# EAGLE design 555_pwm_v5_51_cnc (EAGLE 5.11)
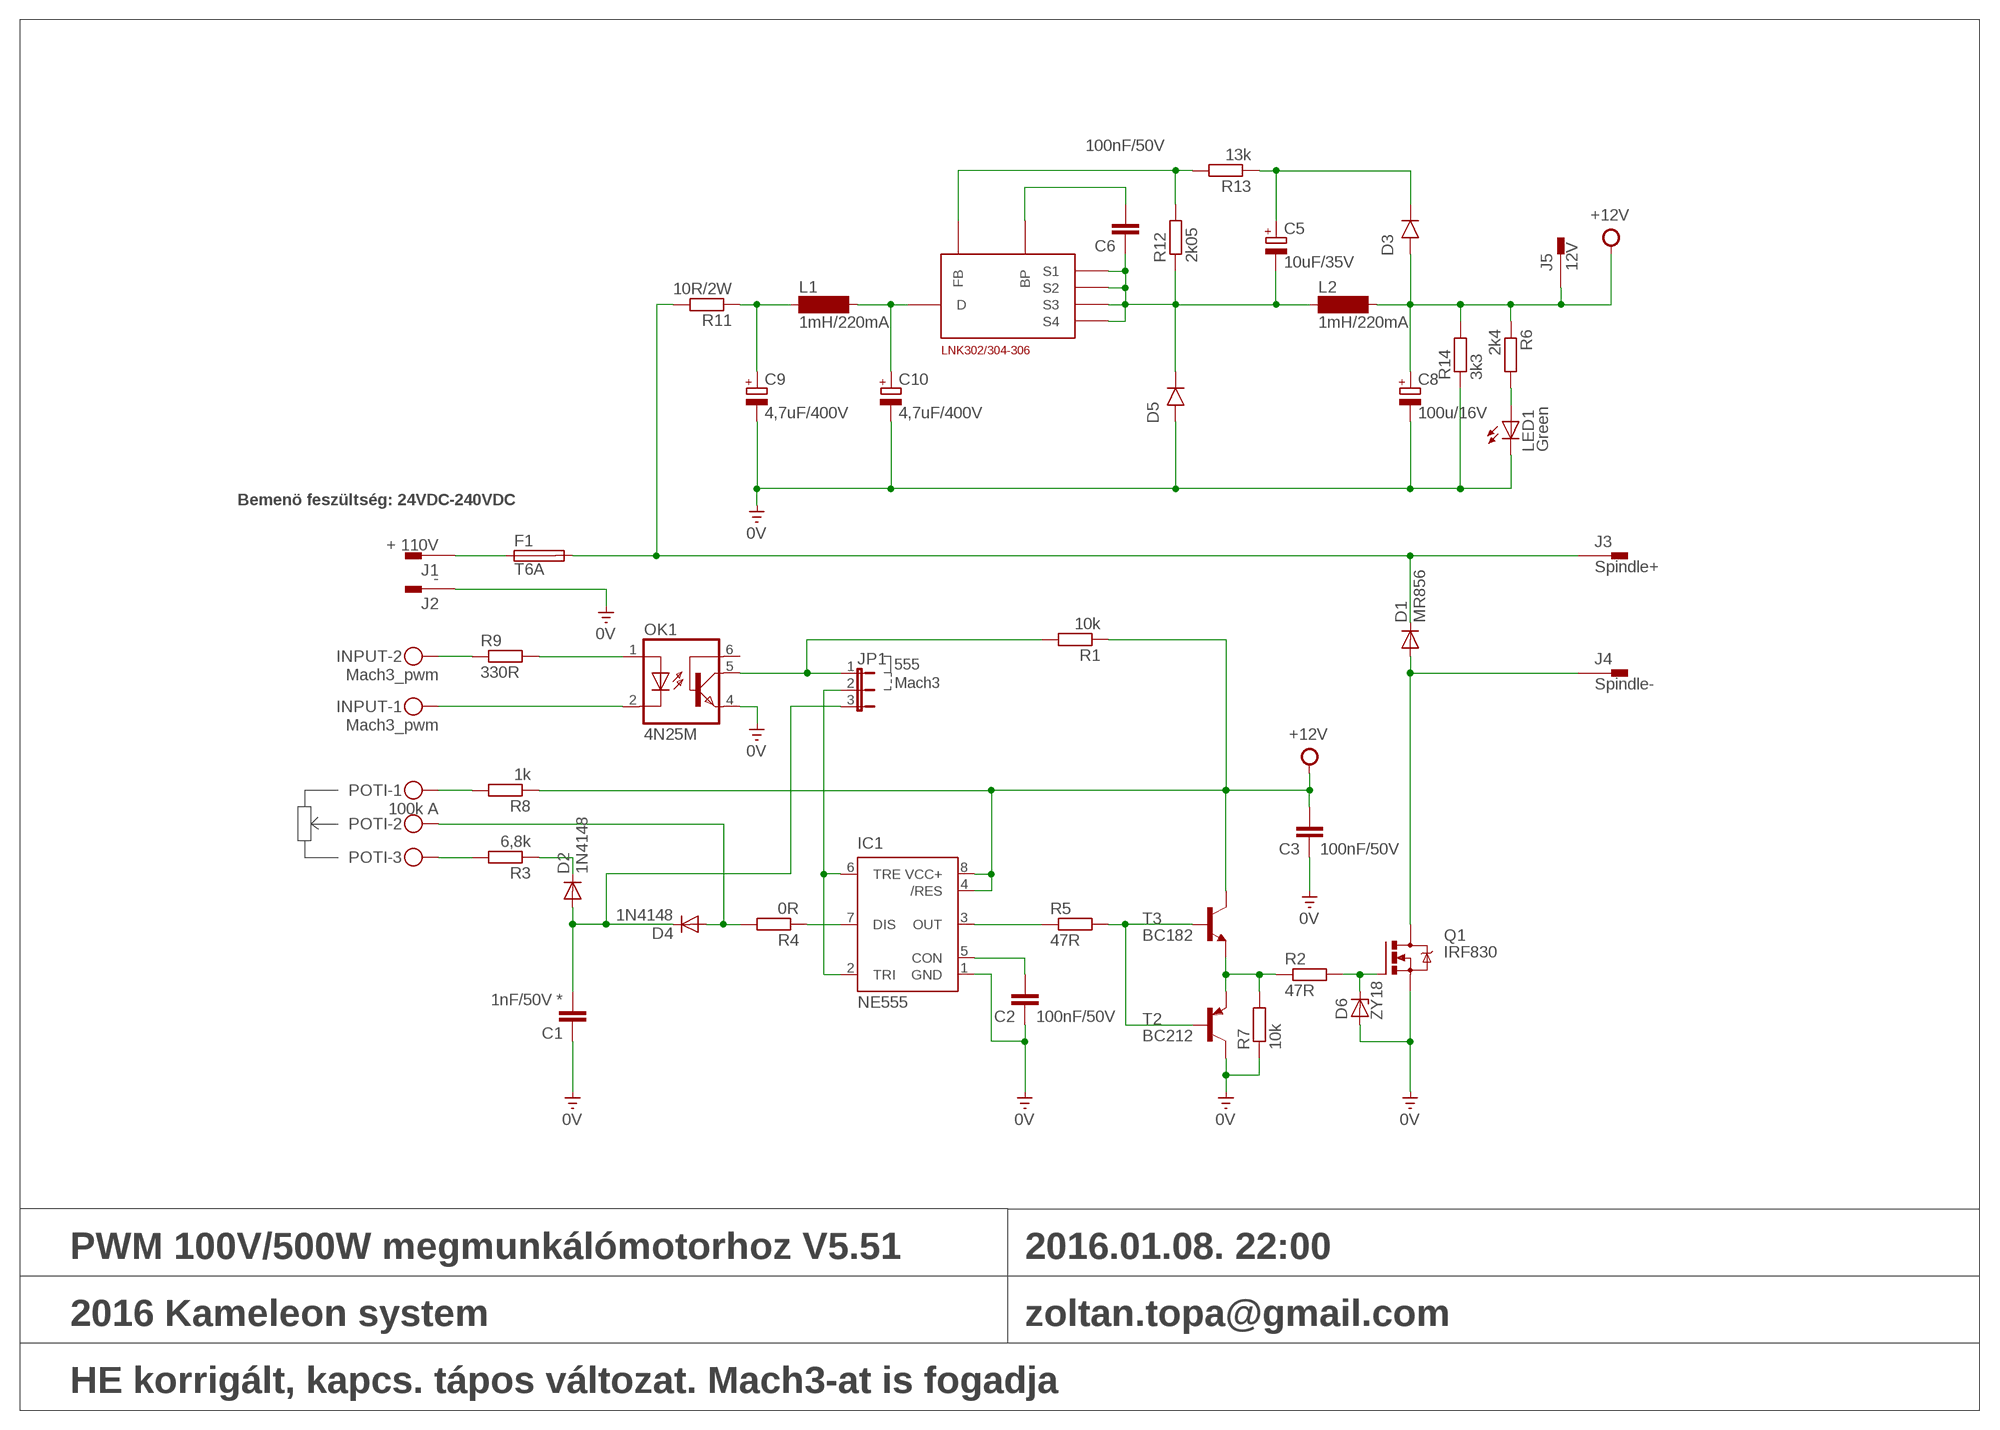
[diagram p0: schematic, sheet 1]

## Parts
C1  1nF/50V *  C-EU025_050-055X075  [C025_050-055X075]
C2  100nF/50V  C-EU025_050-055X075  [C025_050-055X075]
C3  100nF/50V  C-EU025_050-055X075  [C025_050-055X075]
C5  10uF/35V  CPOL-EUE2.5-5  [E2,5-5]
C6  100nF/50V  C-EU025_050-055X075  [C025_050-055X075]
C8  100u/16V  CPOL-EUE2.5-7  [E2,5-7]
C9  4,7uF/400V  CPOL-EUE2.5-7  [E2,5-7]
C10  4,7uF/400V  CPOL-EUE2.5-7  [E2,5-7]
D1  MR856  1N5400  [DO201-15]
D2  1N4148  1N4148DO35-10  [DO35-10]
D3  1N4007  1N4001  [DO41-10]
D4  1N4148  1N4148DO35-10  [DO35-10]
D5  1N4007  1N4001  [DO41-10]
D6  ZY18  ZENER-DIODEDO35Z10  [DO35Z10]
F1  T6A  SH22,5A  [SH22,5A]
IC1  NE555  [DIL-08]
INPUT  Mach3_pwm  MKDSN1,5/2-5,08  [MKDSN1,5/2-5,08]
J1  + 110V  PIN2F061.100  [F061.100]
J2  -  PIN2F061.100  [F061.100]
J3  Spindle+  PIN2F061.100  [F061.100]
J4  Spindle-  PIN2F061.100  [F061.100]
J5  12V  PIN2F061.100  [F061.100]
JP1  JP2E  [JP2]
L1  1mH/220mA  BS11  [BS11]
L2  1mH/220mA  BS11  [BS11]
LED1  Green  LED5MM  [LED5MM]
LNK304PN  LNK304PN  LNK302/304-306DIL_08  [DIL08_LNK]
OK1  4N25M  [DIL06]
POTI  100k A  MKDSN1,5/3-5,08  [MKDSN1,5/3-5,08]
Q1  IRF830  IRF540  [TO220BV]
R1  10k  R-EU_0309/10  [0309/10]
R2  47R  R-EU_0309/10  [0309/10]
R3  6,8k  R-EU_0309/10  [0309/10]
R4  0R  R-EU_0309/10  [0309/10]
R5  47R  R-EU_0309/10  [0309/10]
R6  2k4  R-EU_0309/10  [0309/10]
R7  10k  R-EU_0309/10  [0309/10]
R8  1k  R-EU_0309/10  [0309/10]
R9  330R  R-EU_0309/10  [0309/10]
R11  10R/2W  R-EU_0617/22  [0617/22]
R12  2k05  R-EU_0309/10  [0309/10]
R13  13k  R-EU_0309/10  [0309/10]
R14  3k3  R-EU_0309/10  [0309/10]
T2  BC212  -PNP-TO92-CBE  [TO92-CBE]
T3  BC182  2N4124-NPN-TO92-CBE  [TO92-CBE]

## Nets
0V [power]: C1.1 C2.1 C3.1 C8.- C9.- C10.- D5.A(ANODE) D6.A IC1.1(GND) J2.A1 LED1.K(C) OK1.4(EMI) Q1.S R7.1 R14.1 T2.C
+12V: C3.2 C8.+ D3.A(ANODE) IC1.4(/RES) IC1.8(VCC+) J5.A1 L2.2 R1.1 R6.1 R8.1 R14.2 T3.C
N$2: D6.C Q1.G R2.2
N$3: C9.+ L1.1 R11.1
N$4: D1.A J4.A1 Q1.D
N$5 [power]: D1.C F1.2 J3.A1 R11.2
N$6: C10.+ L1.2 LNK304PN.D
N$7: JP1.1 OK1.5(COL) R1.2
N$8: R2.1 R7.2 T2.E T3.E
N$9: R5.2 T2.B T3.B
N$10: C1.2 D2.A D4.C JP1.3
N$11: IC1.2(TRI) IC1.6(TRE) JP1.2
N$12: D2.C R3.1
N$13: POTI.1 R8.2
N$14: D4.A POTI.2 R4.2
N$15: C2.2 IC1.5(CON)
N$17: OK1.1(A) R9.2
N$18: INPUT.2 R9.1
N$19: INPUT.1 OK1.2(C)
N$21: POTI.3 R3.2
N$22: C6.2 LNK304PN.BP
N$23: C5.- C6.1 D5.C(CATHODE) L2.1 LNK304PN.S1 LNK304PN.S2 LNK304PN.S3 LNK304PN.S4 R12.1
N$24: LNK304PN.FB R12.2 R13.2
N$25: C5.+ D3.C(CATHODE) R13.1
N$26: LED1.A R6.2
N$27 [power]: F1.1 J1.A1
N$28: IC1.7(DIS) R4.1
N$29: IC1.3(OUT) R5.1
Unconnected: J1.A2(1.1) J2.A2(1.1) J3.A2(1.1) J4.A2(1.1) J5.A2(1.1) OK1.6(BAS)

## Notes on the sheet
- Bemenö feszültség: 24VDC-240VDC
- 555
- Mach3
- PWM 100V/500W megmunkálómotorhoz V5.51 | 2016.01.08. 22:00
- 2016 Kameleon system | zoltan.topa@gmail.com
- HE korrigált, kapcs. tápos változat. Mach3-at is fogadja

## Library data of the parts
C1-C3 C6 = Kameleon_2013:C-EU: CAPACITOR, European symbol
C5 C8-C10 = rcl:CPOL-EU: POLARIZED CAPACITOR, European symbol
D1 = diode:1N5400: DIODE
D2 D4 = diode:1N4148: DIODE
D3 D5 = tango:1N4001: DIODE
D6 = diode:ZENER-DIODE: Z-Diode
F1 = fuse:SH22,5A: FUSE HOLDER; MPN: 0031.7701.11; OC_FARNELL: unknown; OC_NEWARK: 04F1224
IC1 = st-microelectronics-2:NE555: General purpose bipolar Timer
INPUT = con-phoenix-508:MKDSN1,5/2-5,08: MKDSN 1,5/ 2-5,08 Printklemme; MPN: MKDSN 1,5/2-5.08; OC_FARNELL: 1792903; OC_NEWARK: 30M2397
J1-J5 = con-faston:PIN2: Flachstecker Typ Tyco/Electronics/AMP TAB, FASTON; OC_FARNELL: unknown; OC_NEWARK: unknown
JP1 = jumper:JP2E: JUMPER
L1 L2 = inductor-neosid:BS: INDUCTOR; OC_FARNELL: unknown; OC_NEWARK: unknown
LED1 = Kameleon_2013:LED: LED
LNK304PN = linkswitch:LNK302/304-306
OK1 = optocoupler:4N*?M: General Purpose 6-Pin Phototransistor Optocouplers Source: http://www.fairchildsemi.com/ds/4N/4N35-M.pdf; MPN: 4N25-M; OC_FARNELL: 1021349; OC_NEWARK: 98K9084
POTI = con-phoenix-508:MKDSN1,5/3-5,08: MKDSN 1,5/ 3-5,08 Printklemme Nennstrom: 13,5 A Nennspannung: 250 V Rastermaß: 5,08 mm Polzahl: 3 Anschlussart: Schraubanschluss Montage: Löten Anschlussrichtung Leiter/Platine: 0 ° Artikelnummer: 1729131 Source: http://eshop.phoenixcontact.com .. 1729131.pdf; MPN: SMKDSN1,5/3-5,08; OC_FARNELL: 1792904; OC_NEWARK: 70R0299
Q1 = transistor-power:IRF540: HEXFET Power MOSFET
R1-R9 R11-R14 = resistor:R-EU_: RESISTOR, European symbol
T2 = transistor-neu-to92:*-PNP-: PNP Transistror
T3 = transistor:*-NPN-: NPN Transistror BF959 corrected 2008.03.06

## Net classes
0 default: width 0.635 mm, drill 0.8 mm
1 power: width 2.032 mm

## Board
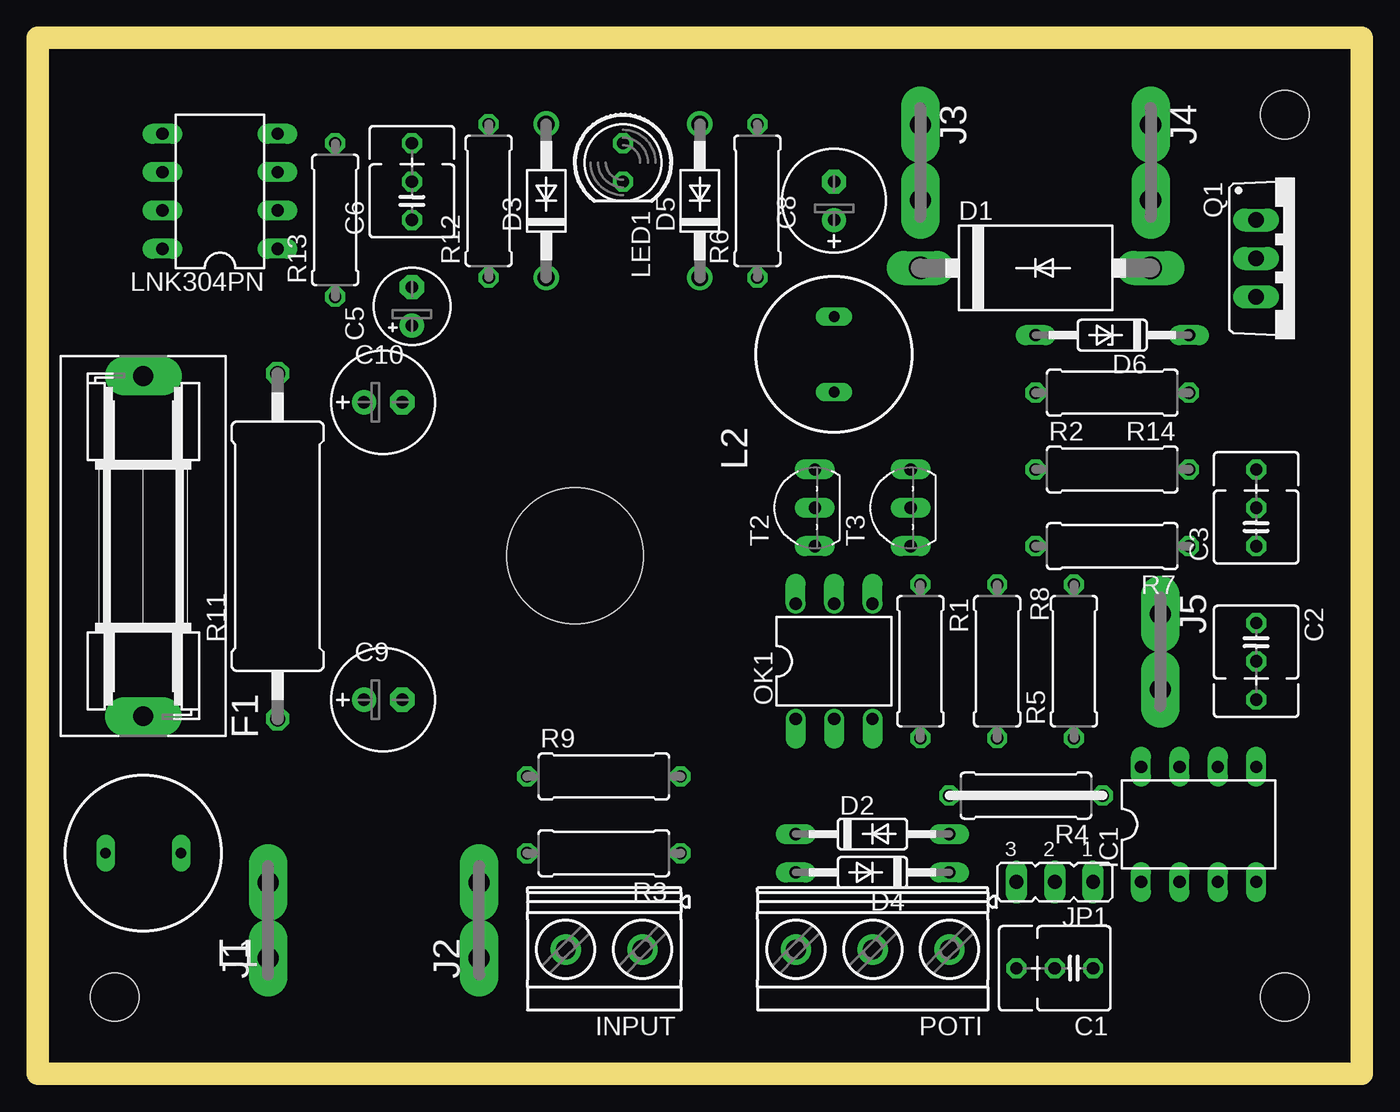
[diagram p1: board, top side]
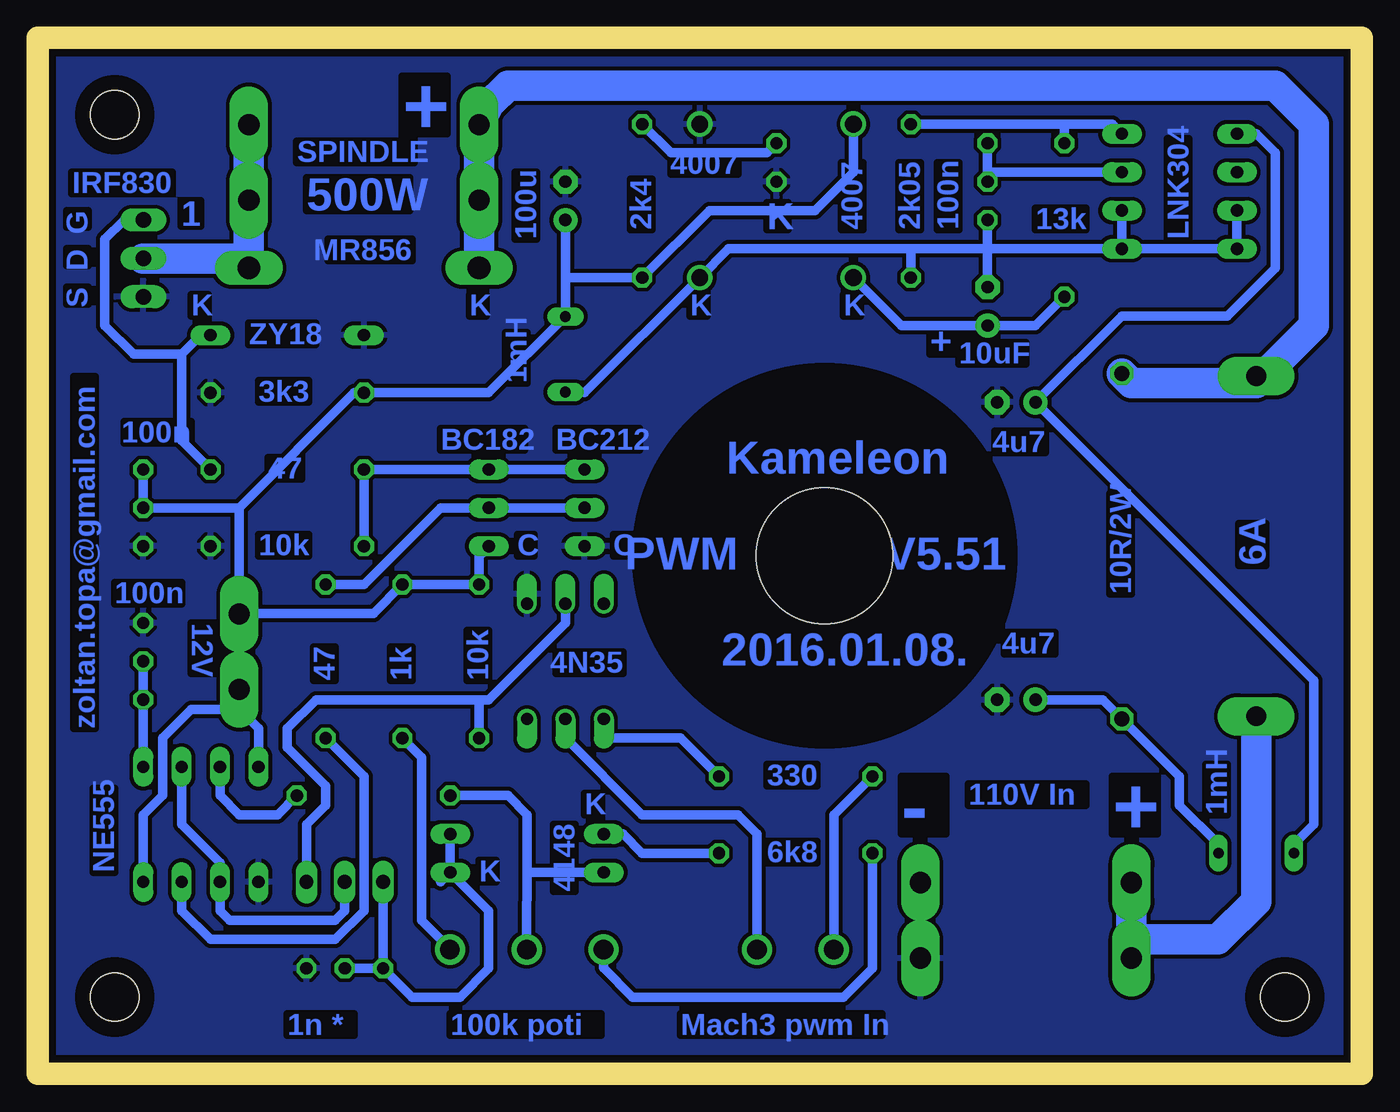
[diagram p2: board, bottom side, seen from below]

Size 87.63 x 68.58 mm. Coordinates in mm from the lower left corner, seen from the top.
Outline: 0,0 87.63,0 87.63,68.58 0,68.58 0,0
Copper layers (1*16): Top 0.035mm / dielectric 1.5mm / Bottom 0.035mm
Design rules "default": minimum track width 10mil, minimum drill 24mil, track to track 8mil, track to pad 8mil, pad to pad 8mil, via to via 8mil, smd to smd 8mil, copper to edge 40mil, drill to drill 8mil, minimum pad ring 10mil, minimum via ring 8mil, stop-mask expansion 4mil, vias tented up to drill 0mil, thermal gap 10mil
Holes 9 mm at 35.56,34.29
Holes 3.2 mm at 82.55,5.08 5.08,5.08 82.55,63.5
bRestrict: area 29.6,28.3 to 41.6,40.3
Milling: 4 lines

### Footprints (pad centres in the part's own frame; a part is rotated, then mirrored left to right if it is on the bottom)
C025_050-055X075 = drill 0.813 octagon: 1 -1.27,0; 2 1.27,0; 3 3.81,0
E2,5-5 = drill 0.813 pad 1.6 round: + -1.27,0 | drill 0.813 pad 1.6 octagon: - 1.27,0
E2,5-7 = drill 0.813 pad 1.6 round: + -1.27,0 | drill 0.813 pad 1.6 octagon: - 1.27,0
DO201-15 = drill 1.499 long: A 7.62,0; C -7.62,0
DO35-10 = drill 0.813 long: A 5.08,0; C -5.08,0
DO41-10 = drill 1.118 round: A 5.08,0; C -5.08,0
DO35Z10 = drill 0.813 long: A 5.08,0; C -5.08,0
SH22,5A = drill 1.321 pad 2.54 long: 1 -11.252,0; 2 11.252,0
DIL-08 = drill 0.813 long: 1 -3.81,-3.81; 2 -1.27,-3.81; 3 1.27,-3.81; 4 3.81,-3.81; 5 3.81,3.81; 6 1.27,3.81; 7 -1.27,3.81; 8 -3.81,3.81
MKDSN1,5/2-5,08 = drill 1.3 pad 2 round: 1 -2.561,0.025; 2 2.519,0.025
F061.100 = drill 1.4 pad 2.54 long: A1 -2.5,0; A2 2.5,0
JP2 = drill 0.914 long: 1 -2.54,0; 2 0,0; 3 2.54,0
BS11 = drill 0.7 long: 1 -2.5,0; 2 2.5,0
LED5MM = drill 0.813 octagon: A -1.27,0; K 1.27,0
DIL08_LNK = drill 0.813 long: BP 1.27,-3.81; D 3.81,3.81; FB 3.81,-3.81; N/C 1.27,3.81; S1 -3.81,-3.81; S2 -1.27,-3.81; S3 -1.27,3.81; S4 -3.81,3.81
DIL06 = drill 0.813 offset: 1 -2.54,-3.81; 2 0,-3.81; 3 2.54,-3.81; 4 2.54,3.81; 5 0,3.81; 6 -2.54,3.81
MKDSN1,5/3-5,08 = drill 1.3 pad 2 round: 1 -7.641,0.025; 2 -2.561,0.025; 3 2.519,0.025
TO220BV = drill 1.016 long: D 0,-2.54; G -2.54,-2.54; S 2.54,-2.54
0309/10 = drill 0.813 octagon: 1 -5.08,0; 2 5.08,0
0617/22 = drill 1.016 octagon: 1 -11.43,0; 2 11.43,0
TO92-CBE = drill 0.813 long: B 0,0; C -2.54,0; E 2.54,0

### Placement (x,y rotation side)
C1  68.58,6.99 180 top
C2  80.64,28.57 270 top
C3  80.64,36.2 90 top
C5  24.77,50.8 90 top
C6  24.77,57.78 90 top
C8  52.7,57.78 90 top
C9  22.86,24.77 0 top
C10  22.86,44.45 0 top
D1  66.04,53.34 0 top
D2  55.24,15.88 0 top
D3  33.66,57.78 90 top
D4  55.24,13.34 180 top
D5  43.81,57.78 90 top
D6  71.12,48.9 180 top
F1  6.99,34.92 90 top
IC1  76.83,16.51 0 top
INPUT  37.47,8.26 180 top
J1  15.24,10.16 90 top
J2  29.21,10.16 90 top
J3  58.42,60.33 270 top
J4  73.66,60.33 270 top
J5  74.3,27.94 270 top
JP1  67.31,12.7 180 top
L1  6.99,14.61 180 top
L2  52.7,47.62 90 top
LED1  38.73,60.33 270 top
LNK304PN  12.06,58.42 90 top
OK1  52.7,27.3 0 top
POTI  52.7,8.26 180 top
Q1  83.19,53.98 270 top
R1  58.42,27.3 270 top
R2  71.12,40.01 0 top
R3  37.47,14.61 180 top
R4  65.41,18.41 180 top
R5  68.58,27.3 90 top
R6  47.62,57.78 90 top
R7  71.12,34.92 180 top
R8  63.5,27.3 270 top
R9  37.47,19.68 0 top
R11  15.88,34.92 90 top
R12  29.84,57.78 90 top
R13  19.68,56.52 90 top
R14  71.12,45.09 180 top
T2  51.44,37.47 90 top
T3  57.78,37.47 90 top

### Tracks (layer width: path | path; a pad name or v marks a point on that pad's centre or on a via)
0V
  pour Bottom (isolate 0.254): -0.64,-0.64 88.27,-0.64 88.27,69.22 -0.64,69.22
+12V
  Bottom 0.635: IC1.4 80.64,17.14 79.38,18.41 79.38,22.23 77.47,24.13 74.3,24.13 | 52.7,50.16 52.7,52.7 | 52.7,52.7 C8.+ | 52.7,50.16 L2.2 | D3.A 33.66,59.69 36.2,57.15 43.18,57.15 R6.1 52.7,52.7 | 72.98,30.48 65.41,30.48 R8.1 R1.1 58.42,34.29 T3.C | 72.98,30.48 74.3,30.48 | 72.98,30.48 J5.A1 | IC1.8 73.03,22.86 74.3,24.13 | 80.64,40.01 C3.2 74.3,37.47 | J5.A1 74.3,37.47 | J5.A1 74.3,24.13 | 52.7,50.16 57.78,45.09 R14.2 66.67,45.09 74.3,37.47
N$2
  Bottom 0.635: Q1.G 81.92,56.52 83.19,55.24 83.19,49.53 81.28,47.62 78.11,47.62 | R2.2 78.11,41.91 78.11,47.62 | 78.11,47.62 76.83,48.9 D6.C
N$3
  Bottom 0.635: C9.+ 17.14,24.77 R11.1 12.06,19.68 12.06,17.78 9.53,15.24 L1.1
N$4
  Bottom 2.032: Q1.D 74.3,53.98 D1.A J4.A1
N$5
  Bottom 2.032: J3.A1 57.78,64.14 56.52,65.41 5.71,65.41 3.17,62.87 3.17,49.53 6.99,45.72 | J3.A1 58.42,62.87 | 6.99,45.72 15.24,45.72 R11.2 | F1.2 7.8,46.35 6.99,45.72 | J3.A1 D1.C
N$6
  Bottom 0.635: LNK304PN.D 6.99,62.23 5.71,60.96 5.71,53.34 8.89,50.16 15.88,50.16 C10.+ 3.17,26.04 3.17,16.51 4.49,15.2 L1.2
N$7
  Bottom 0.635: R1.2 58.42,24.77 | JP1.1 69.85,16.51 68.58,17.78 68.58,19.05 71.12,21.59 71.12,22.86 69.22,24.77 58.42,24.77 | 58.42,24.77 57.78,24.77 52.7,29.84 OK1.5
N$8
  Bottom 0.635: T2.E T3.E R2.1 R7.2
N$9
  Bottom 0.635: T2.B T3.B 60.96,37.47 66.04,32.38 R5.2
N$10
  Bottom 0.635: D4.C D2.A | D4.C 60.96,12.7 | D4.C 57.78,10.79 57.78,6.99 59.69,5.08 62.87,5.08 64.77,6.99 | 64.77,6.99 JP1.3 | 64.77,6.99 C1.2
N$11
  Bottom 0.635: JP1.2 67.31,10.79 67.94,10.16 74.93,10.16 75.56,10.79 IC1.2 75.56,13.97 78.11,16.51 IC1.6
N$12
  Bottom 0.635: R3.1 47.62,14.61 48.9,15.88 D2.C
N$13
  Bottom 0.635: POTI.1 60.35,8.28 62.23,10.16 62.23,20.95 R8.2
N$14
  Bottom 0.635: POTI.2 55.27,10.77 55.24,12.06 55.24,13.34 | 55.24,13.34 55.24,17.14 56.52,18.41 R4.2 | D4.A 55.24,13.34
N$15
  Bottom 0.635: IC1.5 C2.2
N$17
  Bottom 0.635: R9.2 45.09,22.23 50.16,22.23 OK1.1
N$18
  Bottom 0.635: R9.1 34.95,17.12 INPUT.2
N$19
  Bottom 0.635: OK1.2 52.7,22.23 47.62,17.14 41.27,17.14 40.03,15.9 INPUT.1
N$21
  Bottom 0.635: R3.2 32.38,6.99 34.29,5.08 48.26,5.08 50.19,7.01 POTI.3
N$22
  Bottom 0.635: 24.77,59.69 24.77,61.59 | LNK304PN.BP 24.77,59.69 | 24.77,59.69 C6.2
N$23
  Bottom 0.635: LNK304PN.S3 LNK304PN.S4 LNK304PN.S1 | LNK304PN.S1 LNK304PN.S2 | L2.1 51.44,45.09 D5.C 41.91,54.61 29.84,54.61 | 24.77,54.61 C5.- | 24.77,54.61 C6.1 | 29.84,54.61 R12.1 | 24.77,54.61 29.84,54.61 | LNK304PN.S1 24.77,54.61
N$24
  Bottom 0.635: 19.68,62.87 R12.2 | LNK304PN.FB 16.51,62.87 19.68,62.87 | 19.68,62.87 R13.2
N$25
  Bottom 0.635: R13.1 21.59,49.53 C5.+ 30.48,49.53 D3.C
N$26
  Bottom 0.635: LED1.A 39.37,60.96 45.72,60.96 R6.2
N$27
  Bottom 2.032: 15.24,8.89 9.53,8.89 6.99,11.43 F1.1 | 15.24,8.89 J1.A1 15.24,7.62 | 15.24,8.89 15.24,12.7
N$28
  Bottom 0.635: IC1.7 75.56,18.41 74.3,17.14 71.75,17.14 R4.1
N$29
  Bottom 0.635: IC1.3 78.11,10.79 76.2,8.89 67.94,8.89 66.04,10.79 66.04,19.68 R5.1

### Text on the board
Bottom: + | 4007 | SPINDLE | IRF830 | 1 | 500W | G | 13k | 100n | 2k05 | 4007 | K | 2k4 | LNK304 | 100u | MR856 | D | S | K | K | K | K | + | ZY18 | 10uF | 1mH | 3k3 | 4u7 | 100n | Kameleon | BC212 | BC182 | 47 | V5.51 | PWM | 6A | C | C | 10k | 10R/2W | 100n | 12V | 4u7 | 2016.01.08. | 4N35 | 10k | 1k | 47 | zoltan.topa@gmail.com | 330 | 110V In | 1mH | K | + | - | 6k8 | K | NE555 | 4148 | Mach3 pwm In | 100k poti | 1n *
tValues: K | G D S | 1 | K | K | K | K | K | K
bStop: + | 4007 | SPINDLE | IRF830 | 1 | 500W | G | 13k | 100n | 2k05 | 4007 | K | 2k4 | LNK304 | 100u | MR856 | D | S | K | K | K | K | + | ZY18 | 10uF | 1mH | 3k3 | 4u7 | 100n | Kameleon | BC212 | BC182 | 47 | V5.51 | PWM | 6A | C | C | 10k | 10R/2W | 100n | 12V | 4u7 | 2016.01.08. | 4N35 | 10k | 1k | 47 | zoltan.topa@gmail.com | 330 | 110V In | 1mH | K | + | - | 6k8 | K | NE555 | 4148 | Mach3 pwm In | 100k poti | 1n *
